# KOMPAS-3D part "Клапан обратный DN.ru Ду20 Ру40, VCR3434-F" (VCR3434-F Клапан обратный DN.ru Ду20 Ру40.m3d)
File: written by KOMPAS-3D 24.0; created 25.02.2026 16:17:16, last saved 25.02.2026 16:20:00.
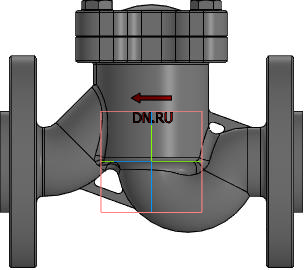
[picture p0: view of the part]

Document properties: Автор: R2D2; Полное имя файла: VCR3434-F Клапан обратный DN.ru Ду20 Ру40.cdw

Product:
- Body: Тело 2  | qty 1
    Масса: 4.256857
- Part/product: Клапан обратный DN.ru Ду20 Ру40  | designation VCR3434-F
    Масса: 3.7
    Раздел спецификации: Прочие изделия
    Форматы листов документа: A3
    Примечание: D100-04051
    additional columns: D100-04051

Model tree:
1. Операция без истории:1
2. Эскиз:1
3. Элемент выдавливания:1  (with: Грань.Операция без истории:1)
     Расстояние 1 = 28.8427; Смещение 1 = 0.5
4. Элемент выдавливания:2  (with: Грань.Операция без истории:1)
     Расстояние 1 = 19.4997
5. Скругление:1  (with: Ребро.Операция без истории:1, Ребро.Элемент выдавливания:2)
     Радиус = 3

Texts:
  VCR3434-F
